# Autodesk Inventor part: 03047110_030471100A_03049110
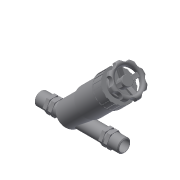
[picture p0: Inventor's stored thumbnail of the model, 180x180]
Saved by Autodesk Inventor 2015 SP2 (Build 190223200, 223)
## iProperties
Created: 2017-05
Part Number: 03047110_030471100A_03049110
Material: Generic
Description: PLASSON ANGLE SEAT VALVE 1"-1"
Document SubType Name: Modeling
Designer: KIM
Density: 1 g/cm^3
Appearance: Default
Author: KIM
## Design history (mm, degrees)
derived "03049.ipt"
feature "Solid1::03049.ipt"
tag "TaggingFeature1"
body "Solid1"
other parameters: "d1" = 33.249, "d2" = 36, "d3" = 26.5992, "d6" = 17, "d8" = 1.7, "d12" = 0, "d14" = -8.5, "d15" = 3.4, "d16" = 0, "d17" = 41.58, "d18" = 5.04, "d19" = 138.6, "d20" = 50.4, "d21" = 135 deg, "d22" = 53.55, "d23" = 25.2, "d24" = 59.85, "d25" = 15.12, "d26" = 90 deg, "d27" = 44.1, "d28" = 70 deg, "d29" = 18.9, "d30" = 15.12, "d31" = 18.9, "d32" = 63, "d33" = 44.1, "d34" = 135 deg, "d35" = 2, "d36" = 126, "d39" = 59.5, "d40" = 1.4, "d41" = 1, "d42" = 1, "d43" = 4.2, "d44" = 4.2, "d46" = 0, "d48" = 360 deg, "d50" = 0.7, "d51" = 0.7, "d53" = 360 deg, "d69" = 53.55, "d70" = 4.2, "d71" = 4.2, "d72" = 8.4, "d74" = 0, "d75" = 0.7, "d77" = 360 deg, "d80" = 58.0545, "d81" = 5.6, "d82" = 2.8, "d83" = 22.68, "d84" = 0, "d86" = 360 deg, "d88" = 1.4, "R_" = 33.249, "E_" = 36, "d13" = 17, "d67" = 63, "d68" = 44.1, "d79" = 59.85
